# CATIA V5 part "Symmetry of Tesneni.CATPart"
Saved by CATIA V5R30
Part number: Symmetry of Tesneni
Bounding box of the stored display mesh (mm): x 0 to 1.2, y -6 to 6, z -6 to 6
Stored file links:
  E:\Bakalarka\Model\Forma_v7\Symmetry of Tesneni.CATPart
  E:\Bakalarka\Model\Forma_v7\Tesneni.CATPart
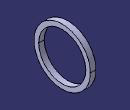
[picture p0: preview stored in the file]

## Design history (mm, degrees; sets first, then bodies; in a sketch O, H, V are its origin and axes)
Body1 (main body)
  Body2 "Body from original PartBody"
    Solid1: linked copy from another document
  Assemble1: tool Body2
